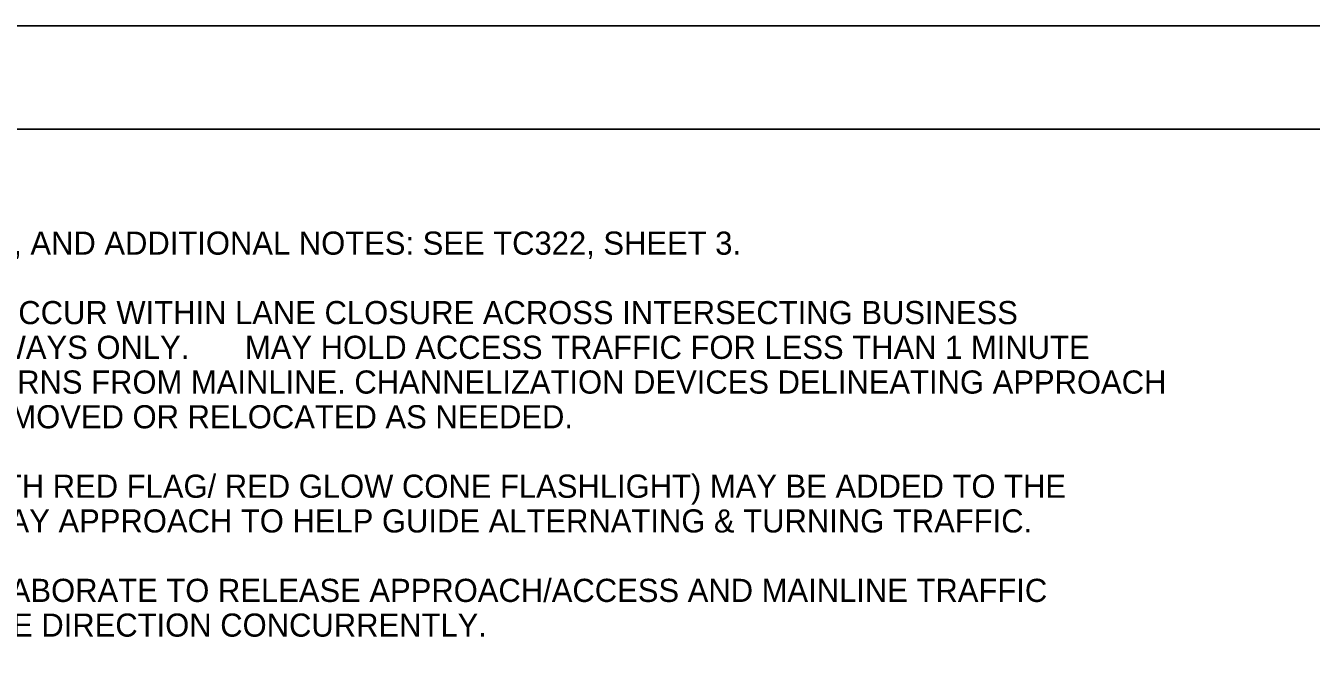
# Model space of a CAD drawing. Extents: x 99999.1 to 100095.7, y 99995 to 100010.7.
# Drawn here: x 100061.313 to 100065.2, y 100008.726 to 100010.687 of the extents above; entities that cross this region are included whole.
import ezdxf

# ---------------------------------------------------------------- set-up
doc = ezdxf.new("R2010")
doc.units = 0
for name, color, linetype in [('SH_GI_GeneralNotesBodyText', 7, 'Continuous'), ('SH_GI_PlotLimits', 7, 'Continuous'), ('SH_GI_SheetBorder', 7, 'Continuous')]:
    doc.layers.add(name, color=color, linetype=linetype)

msp = doc.modelspace()

# ---------------------------------------------------------------- linework, layer by layer
at = {"layer": 'SH_GI_PlotLimits'}
msp.add_lwpolyline([(100059.0625, 99999.6875), (100076.0625, 99999.6875), (100076.0625, 100010.6875), (100059.0625, 100010.6875)], close=True, dxfattribs=at)
at = {"layer": 'SH_GI_SheetBorder'}
msp.add_line((100060, 100010.375), (100075.75, 100010.375), dxfattribs=at)

# ---------------------------------------------------------------- texts
at = {"layer": 'SH_GI_GeneralNotesBodyText'}
for s, p in [('11. FOR LEGEND, TABLES, AND ADDITIONAL NOTES: SEE TC322, SHEET 3.', (100060.1, 100009.995)), ('12. WORK MAY BRIEFLY OCCUR WITHIN LANE CLOSURE ACROSS INTERSECTING BUSINESS ', (100060.1, 100009.785)), ('ACCESSES AND DRIVEWAYS ONLY. ', (100060.18, 100009.68)), ('MAY HOLD ACCESS TRAFFIC FOR LESS THAN 1 MINUTE', (100061.9762, 100009.68)), ('WHILE RESTRICTING TURNS FROM MAINLINE. CHANNELIZATION DEVICES DELINEATING APPROACH ', (100060.18, 100009.575)), ('OR ACCESS MAY BE REMOVED OR RELOCATED AS NEEDED.', (100060.18, 100009.47)), ('13. SINGLE FLAGGER (WITH RED FLAG/ RED GLOW CONE FLASHLIGHT) MAY BE ADDED TO THE ', (100060.1, 100009.26)), ('INTERSECTING ROADWAY APPROACH TO HELP GUIDE ALTERNATING & TURNING TRAFFIC.', (100060.18, 100009.155)), ('14. FLAGGERS MAY COLLABORATE TO RELEASE APPROACH/ACCESS AND MAINLINE TRAFFIC ', (100060.1, 100008.945)), ('TRAVELING IN THE SAME DIRECTION CONCURRENTLY.', (100060.18, 100008.84))]:
    msp.add_text(s, height=0.07, rotation=360, dxfattribs=at).set_placement(p)

doc.saveas('drawing.dxf')
